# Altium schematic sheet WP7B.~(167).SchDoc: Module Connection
size C; DrawnBy: S. X. Wu; Revision: 1.0; SheetNumber: 2; SheetTotal: 2
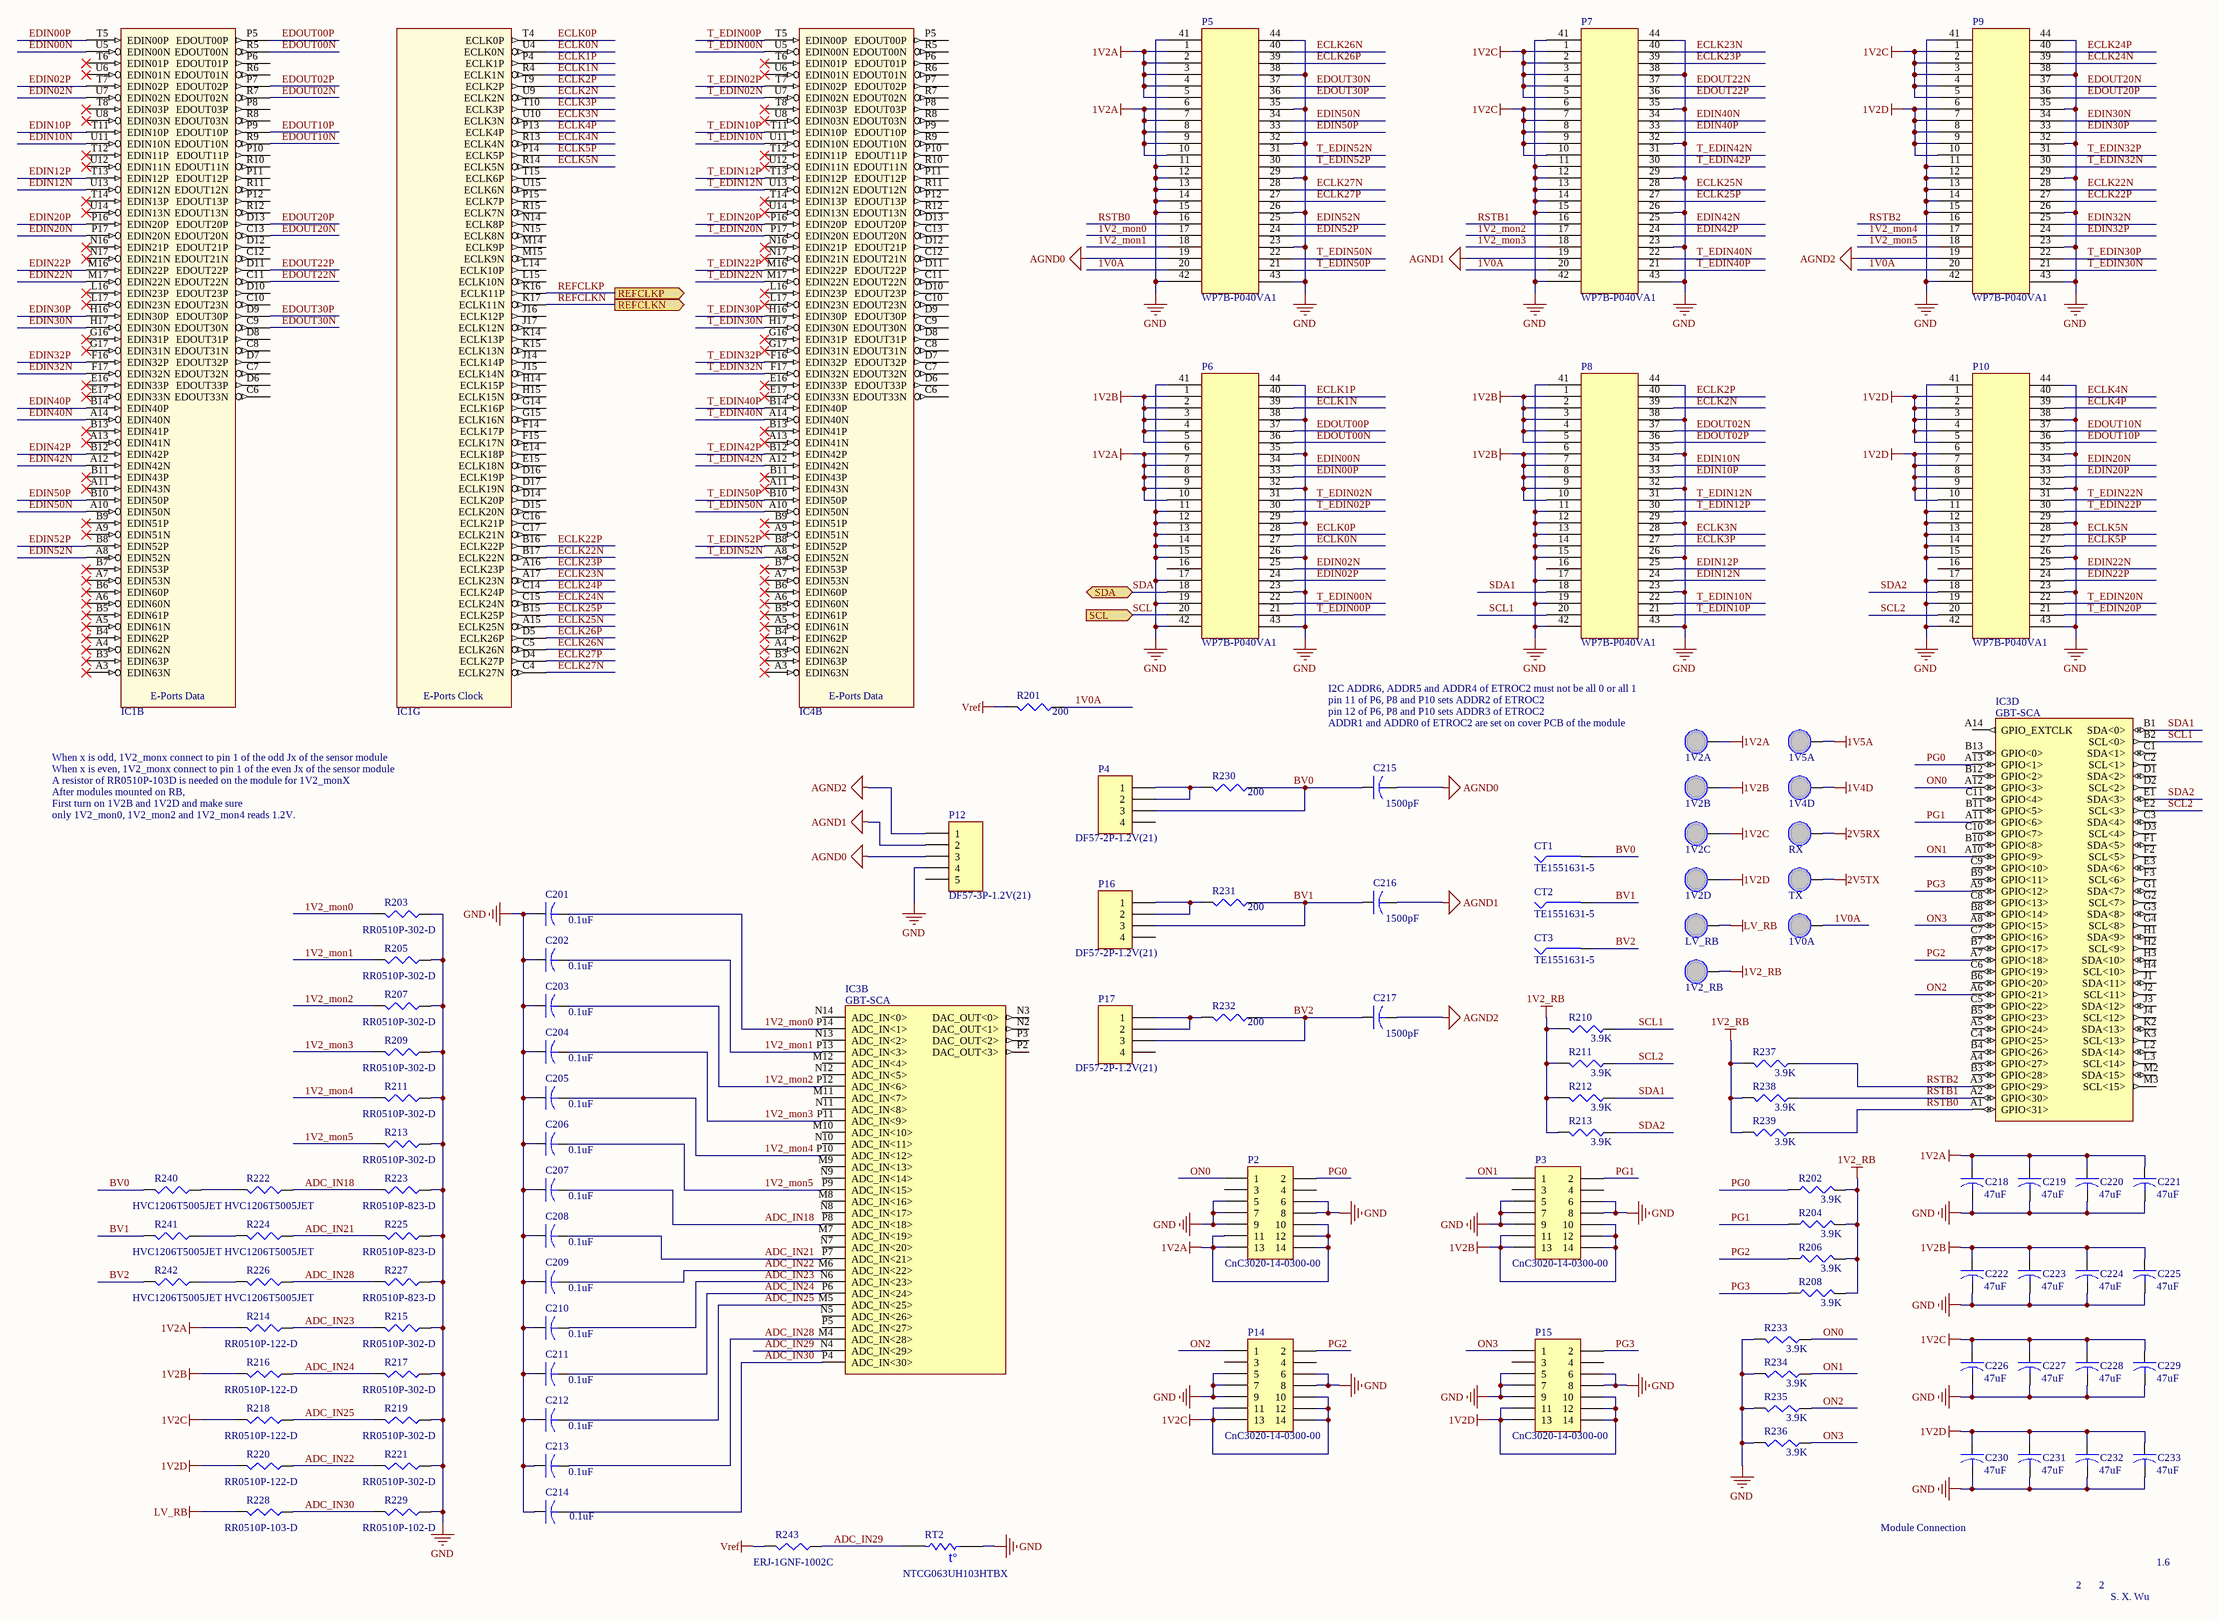
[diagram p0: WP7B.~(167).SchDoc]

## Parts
(Parts that share a designator on the sheet are numbered #1, #2 ... from top to bottom, then left to right.)
C201  value 0.1uF  [capc1005n]  (hidden comment: GRM155R71E104ME14D)
C202  value 0.1uF  [capc1005n]  (hidden comment: GRM155R71E104ME14D)
C203  value 0.1uF  [capc1005n]  (hidden comment: GRM155R71E104ME14D)
C204  value 0.1uF  [capc1005n]  (hidden comment: GRM155R71E104ME14D)
C205  value 0.1uF  [capc1005n]  (hidden comment: GRM155R71E104ME14D)
C206  value 0.1uF  [capc1005n]  (hidden comment: GRM155R71E104ME14D)
C207  value 0.1uF  [capc1005n]  (hidden comment: GRM155R71E104ME14D)
C208  value 0.1uF  [capc1005n]  (hidden comment: GRM155R71E104ME14D)
C209  value 0.1uF  [capc1005n]  (hidden comment: GRM155R71E104ME14D)
C210  value 0.1uF  [capc1005n]  (hidden comment: GRM155R71E104ME14D)
C211  value 0.1uF  [capc1005n]  (hidden comment: GRM155R71E104ME14D)
C212  value 0.1uF  [capc1005n]  (hidden comment: GRM155R71E104ME14D)
C213  value 0.1uF  [capc1005n]  (hidden comment: GRM155R71E104ME14D)
C214  value 0.1uF  [capc1005n]  (hidden comment: GRM155R71E104ME14D)
C215  value 1500pF  [venkel0805]  (hidden comment: C0805X7R102-152MNE)
C216  value 1500pF  [venkel0805]  (hidden comment: C0805X7R102-152MNE)
C217  value 1500pF  [venkel0805]  (hidden comment: C0805X7R102-152MNE)
C218  value 47uF  [capc2012n]  (hidden comment: GRM188R60J476ME15D)
C219  value 47uF  [capc2012n]  (hidden comment: GRM188R60J476ME15D)
C220  value 47uF  [capc2012n]  (hidden comment: GRM188R60J476ME15D)
C221  value 47uF  [capc2012n]  (hidden comment: GRM188R60J476ME15D)
C222  value 47uF  [capc2012n]  (hidden comment: GRM188R60J476ME15D)
C223  value 47uF  [capc2012n]  (hidden comment: GRM188R60J476ME15D)
C224  value 47uF  [capc2012n]  (hidden comment: GRM188R60J476ME15D)
C225  value 47uF  [capc2012n]  (hidden comment: GRM188R60J476ME15D)
C226  value 47uF  [capc2012n]  (hidden comment: GRM188R60J476ME15D)
C227  value 47uF  [capc2012n]  (hidden comment: GRM188R60J476ME15D)
C228  value 47uF  [capc2012n]  (hidden comment: GRM188R60J476ME15D)
C229  value 47uF  [capc2012n]  (hidden comment: GRM188R60J476ME15D)
C230  value 47uF  [capc2012n]  (hidden comment: GRM188R60J476ME15D)
C231  value 47uF  [capc2012n]  (hidden comment: GRM188R60J476ME15D)
C232  value 47uF  [capc2012n]  (hidden comment: GRM188R60J476ME15D)
C233  value 47uF  [capc2012n]  (hidden comment: GRM188R60J476ME15D)
CT1  TE1551631-5  [contact]
CT2  TE1551631-5  [contact]
CT3  TE1551631-5  [contact]
IC1  LPGBT  [BGA289X17]  (value not drawn)  (parts B,G of 8)
IC3  GBT-SCA  [bga196x14]  (parts B,D of 6)
IC4  LPGBT  [BGA289X17]  (value not drawn)  (part B of 8)
P2  CnC3020-14-0300-00  [cnc14]
P3  CnC3020-14-0300-00  [cnc14]
P4  DF57-2P-1.2V(21)  [DF57-2]
P5  WP7B-P040VA1  [wp7b-40p]
P6  WP7B-P040VA1  [wp7b-40p]
P7  WP7B-P040VA1  [wp7b-40p]
P8  WP7B-P040VA1  [wp7b-40p]
P9  WP7B-P040VA1  [wp7b-40p]
P10  WP7B-P040VA1  [wp7b-40p]
P12  DF57-3P-1.2V(21)  [DF57-3]
P14  CnC3020-14-0300-00  [cnc14]
P15  CnC3020-14-0300-00  [cnc14]
P16  DF57-2P-1.2V(21)  [DF57-2]
P17  DF57-2P-1.2V(21)  [DF57-2]
R201  Parameter 1: 200  [resc1005n]  (hidden comment: ERJ-2GEJ201X)
R202  Parameter 1: 3.9K  [resc1005n]  (hidden comment: ERJ-2GEJ392X)
R203  RR0510P-302-D  [resc1005n]
R204  Parameter 1: 3.9K  [resc1005n]  (hidden comment: ERJ-2GEJ392X)
R205  RR0510P-302-D  [resc1005n]
R206  Parameter 1: 3.9K  [resc1005n]  (hidden comment: ERJ-2GEJ392X)
R207  RR0510P-302-D  [resc1005n]
R208  Parameter 1: 3.9K  [resc1005n]  (hidden comment: ERJ-2GEJ392X)
R209  RR0510P-302-D  [resc1005n]
R210  Parameter 1: 3.9K  [resc1005n]  (hidden comment: ERJ-2GEJ392X)
R211#1  Parameter 1: 3.9K  [resc1005n]  (hidden comment: ERJ-2GEJ392X)
R211#2  RR0510P-302-D  [resc1005n]
R212  Parameter 1: 3.9K  [resc1005n]  (hidden comment: ERJ-2GEJ392X)
R213#1  Parameter 1: 3.9K  [resc1005n]  (hidden comment: ERJ-2GEJ392X)
R213#2  RR0510P-302-D  [resc1005n]
R214  RR0510P-122-D  [resc1005n]
R215  RR0510P-302-D  [resc1005n]
R216  RR0510P-122-D  [resc1005n]
R217  RR0510P-302-D  [resc1005n]
R218  RR0510P-122-D  [resc1005n]
R219  RR0510P-302-D  [resc1005n]
R220  RR0510P-122-D  [resc1005n]
R221  RR0510P-302-D  [resc1005n]
R222  HVC1206T5005JET  [resc3216n]
R223  RR0510P-823-D  [resc1005n]
R224  HVC1206T5005JET  [resc3216n]
R225  RR0510P-823-D  [resc1005n]
R226  HVC1206T5005JET  [resc3216n]
R227  RR0510P-823-D  [resc1005n]
R228  RR0510P-103-D  [resc1005n]
R229  RR0510P-102-D  [resc1005n]
R230  Parameter 1: 200  [resc1005n]  (hidden comment: ERJ-2GEJ201X)
R231  Parameter 1: 200  [resc1005n]  (hidden comment: ERJ-2GEJ201X)
R232  Parameter 1: 200  [resc1005n]  (hidden comment: ERJ-2GEJ201X)
R233  Parameter 1: 3.9K  [resc1005n]  (hidden comment: ERJ-2GEJ392X)
R234  Parameter 1: 3.9K  [resc1005n]  (hidden comment: ERJ-2GEJ392X)
R235  Parameter 1: 3.9K  [resc1005n]  (hidden comment: ERJ-2GEJ392X)
R236  Parameter 1: 3.9K  [resc1005n]  (hidden comment: ERJ-2GEJ392X)
R237  Parameter 1: 3.9K  [resc1005n]  (hidden comment: ERJ-2GEJ392X)
R238  Parameter 1: 3.9K  [resc1005n]  (hidden comment: ERJ-2GEJ392X)
R239  Parameter 1: 3.9K  [resc1005n]  (hidden comment: ERJ-2GEJ392X)
R240  HVC1206T5005JET  [resc3216n]
R241  HVC1206T5005JET  [resc3216n]
R242  HVC1206T5005JET  [resc3216n]
R243  ERJ-1GNF-1002C  [resc0603]
RT2  NTCG063UH103HTBX  [resc0603]
TP1  1V2A  [testpoint]  (no BOM)
TP2  1V2B  [testpoint]  (no BOM)
TP3  1V2C  [testpoint]  (no BOM)
TP4  1V2D  [testpoint]  (no BOM)
TP5  LV_RB  [testpoint]  (no BOM)
TP6  1V2_RB  [testpoint]  (no BOM)
TP7  1V5A  [testpoint]  (no BOM)
TP8  1V4D  [testpoint]  (no BOM)
TP9  RX  [testpoint]  (no BOM)
TP10  TX  [testpoint]  (no BOM)
TP11  1V0A  [testpoint]  (no BOM)

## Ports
REFCLKN (out), REFCLKP (out), SCL (in), SDA (bidir)

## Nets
1V2_RB: R202.2 R204.2 R206.2 R208.2 R210.2 R211#1.2 R212.2 R213#1.2 R237.2 R238.2 R239.2 TP6.1(TP)
1V2A: C218.1 C219.1 C220.1 C221.1 P2.10 P2.11 P2.12 P2.13 P2.14 P5.1 P5.2 P5.3 P5.4 P5.5 P5.6 P5.7 P5.8 P5.9 P5.10 P6.6 P6.7 P6.8 P6.9 P6.10 R214.2 TP1.1(TP)
1V2B: C222.1 C223.1 C224.1 C225.1 P3.10 P3.11 P3.12 P3.13 P3.14 P6.1 P6.2 P6.3 P6.4 P6.5 P8.1 P8.2 P8.3 P8.4 P8.5 P8.6 P8.7 P8.8 P8.9 P8.10 R216.2 TP2.1(TP)
1V2C: C226.1 C227.1 C228.1 C229.1 P7.1 P7.2 P7.3 P7.4 P7.5 P7.6 P7.7 P7.8 P7.9 P7.10 P9.1 P9.2 P9.3 P9.4 P9.5 P14.10 P14.11 P14.12 P14.13 P14.14 R218.2 TP3.1(TP)
1V2D: C230.1 C231.1 C232.1 C233.1 P9.6 P9.7 P9.8 P9.9 P9.10 P10.1 P10.2 P10.3 P10.4 P10.5 P10.6 P10.7 P10.8 P10.9 P10.10 P15.10 P15.11 P15.12 P15.13 P15.14 R220.2 TP4.1(TP)
1V4D: TP8.1(TP)
1V5A: TP7.1(TP)
2V5RX: TP9.1(TP)
2V5TX: TP10.1(TP)
AGND0: C215.2 P5.19 P12.3
AGND1: C216.2 P7.19 P12.2
AGND2: C217.2 P9.19 P12.1
GND: C201.1 C202.1 C203.1 C204.1 C205.1 C206.1 C207.1 C208.1 C209.1 C210.1 C211.1 C212.1 C213.1 C214.1 C218.2 C219.2 C220.2 C221.2 C222.2 C223.2 C224.2 C225.2 C226.2 C227.2 C228.2 C229.2 C230.2 C231.2 C232.2 C233.2 P2.5 P2.6 P2.7 P2.8 P2.9 P3.5 P3.6 P3.7 P3.8 P3.9 P5.11 P5.12 P5.13 P5.14 P5.15 P5.23 P5.26 P5.29 P5.32 P5.35 P5.38 P5.41 P5.42 P5.43 P5.44 P6.11 P6.12 P6.13 P6.14 P6.15 P6.17 P6.19 P6.23 P6.26 P6.29 P6.32 P6.35 P6.38 P6.41 P6.42 P6.43 P6.44 P7.11 P7.12 P7.13 P7.14 P7.15 P7.23 P7.26 P7.29 P7.32 P7.35 P7.38 P7.41 P7.42 P7.43 P7.44 P8.11 P8.12 P8.13 P8.14 P8.15 P8.17 P8.19 P8.23 P8.26 P8.29 P8.32 P8.35 P8.38 P8.41 P8.42 P8.43 P8.44 P9.11 P9.12 P9.13 P9.14 P9.15 P9.23 P9.26 P9.29 P9.32 P9.35 P9.38 P9.41 P9.42 P9.43 P9.44 P10.11 P10.12 P10.13 P10.14 P10.15 P10.17 P10.19 P10.23 P10.26 P10.29 P10.32 P10.35 P10.38 P10.41 P10.42 P10.43 P10.44 P12.4 P14.5 P14.6 P14.7 P14.8 P14.9 P15.5 P15.6 P15.7 P15.8 P15.9 R203.1 R205.1 R207.1 R209.1 R211#2.1 R213#2.1 R215.1 R217.1 R219.1 R221.1 R223.1 R225.1 R227.1 R229.1 R233.2 R234.2 R235.2 R236.2 RT2.1
LV_RB: R228.2 TP5.1(TP)
Vref: R201.2 R243.2
1V0A: P5.20 P7.20 P9.20 R201.1 TP11.1(TP)
1V2_mon0: C201.2 IC3.P14(ADC_IN<1>) P5.17 R203.2
1V2_mon1: C202.2 IC3.P13(ADC_IN<3>) P5.18 R205.2
1V2_mon2: C203.2 IC3.P12(ADC_IN<6>) P7.17 R207.2
1V2_mon3: C204.2 IC3.P11(ADC_IN<9>) P7.18 R209.2
1V2_mon4: C205.2 IC3.P10(ADC_IN<12>) P9.17 R211#2.2
1V2_mon5: C206.2 IC3.P9(ADC_IN<15>) P9.18 R213#2.2
ADC_IN18: C207.2 IC3.P8(ADC_IN<18>) R222.1 R223.2
ADC_IN21: C208.2 IC3.P7(ADC_IN<21>) R224.1 R225.2
ADC_IN22: C209.2 IC3.M6(ADC_IN<22>) R220.1 R221.2
ADC_IN23: C210.2 IC3.N6(ADC_IN<23>) R214.1 R215.2
ADC_IN24: C211.2 IC3.P6(ADC_IN<24>) R216.1 R217.2
ADC_IN25: C212.2 IC3.M5(ADC_IN<25>) R218.1 R219.2
ADC_IN28: C213.2 IC3.M4(ADC_IN<28>) R226.1 R227.2
ADC_IN29: IC3.N4(ADC_IN<29>) R243.1 RT2.2
ADC_IN30: C214.2 IC3.P4(ADC_IN<30>) R228.1 R229.2
BV0: C215.1 CT1.1 P4.3 R230.1 R240.2
BV1: C216.1 CT2.1 P16.3 R231.1 R241.2
BV2: C217.1 CT3.1 P17.3 R232.1 R242.2
ECLK0N: IC1.U4(ECLK0N) P6.27
ECLK0P: IC1.T4(ECLK0P) P6.28
ECLK1N: IC1.R4(ECLK1N) P6.39
ECLK1P: IC1.P4(ECLK1P) P6.40
ECLK2N: IC1.U9(ECLK2N) P8.39
ECLK2P: IC1.T9(ECLK2P) P8.40
ECLK3N: IC1.U10(ECLK3N) P8.28
ECLK3P: IC1.T10(ECLK3P) P8.27
ECLK4N: IC1.R13(ECLK4N) P10.40
ECLK4P: IC1.P13(ECLK4P) P10.39
ECLK5N: IC1.R14(ECLK5N) P10.28
ECLK5P: IC1.P14(ECLK5P) P10.27
ECLK22N: IC1.B17(ECLK22N) P9.28
ECLK22P: IC1.B16(ECLK22P) P9.27
ECLK23N: IC1.A17(ECLK23N) P7.40
ECLK23P: IC1.A16(ECLK23P) P7.39
ECLK24N: IC1.C15(ECLK24N) P9.39
ECLK24P: IC1.C14(ECLK24P) P9.40
ECLK25N: IC1.A15(ECLK25N) P7.28
ECLK25P: IC1.B15(ECLK25P) P7.27
ECLK26N: IC1.C5(ECLK26N) P5.40
ECLK26P: IC1.D5(ECLK26P) P5.39
ECLK27N: IC1.C4(ECLK27N) P5.28
ECLK27P: IC1.D4(ECLK27P) P5.27
EDIN00N: IC1.U5(EDIN00N) P6.34
EDIN00P: IC1.T5(EDIN00P) P6.33
EDIN02N: IC1.U7(EDIN02N) P6.25
EDIN02P: IC1.T7(EDIN02P) P6.24
EDIN10N: IC1.U11(EDIN10N) P8.34
EDIN10P: IC1.T11(EDIN10P) P8.33
EDIN12N: IC1.U13(EDIN12N) P8.24
EDIN12P: IC1.T13(EDIN12P) P8.25
EDIN20N: IC1.P17(EDIN20N) P10.34
EDIN20P: IC1.P16(EDIN20P) P10.33
EDIN22N: IC1.M17(EDIN22N) P10.25
EDIN22P: IC1.M16(EDIN22P) P10.24
EDIN30N: IC1.H17(EDIN30N) P9.34
EDIN30P: IC1.H16(EDIN30P) P9.33
EDIN32N: IC1.F17(EDIN32N) P9.25
EDIN32P: IC1.F16(EDIN32P) P9.24
EDIN40N: IC1.A14(EDIN40N) P7.34
EDIN40P: IC1.B14(EDIN40P) P7.33
EDIN42N: IC1.A12(EDIN42N) P7.25
EDIN42P: IC1.B12(EDIN42P) P7.24
EDIN50N: IC1.A10(EDIN50N) P5.34
EDIN50P: IC1.B10(EDIN50P) P5.33
EDIN52N: IC1.A8(EDIN52N) P5.25
EDIN52P: IC1.B8(EDIN52P) P5.24
EDOUT00N: IC1.R5(EDOUT00N) P6.36
EDOUT00P: IC1.P5(EDOUT00P) P6.37
EDOUT02N: IC1.R7(EDOUT02N) P8.37
EDOUT02P: IC1.P7(EDOUT02P) P8.36
EDOUT10N: IC1.R9(EDOUT10N) P10.37
EDOUT10P: IC1.P9(EDOUT10P) P10.36
EDOUT20N: IC1.C13(EDOUT20N) P9.37
EDOUT20P: IC1.D13(EDOUT20P) P9.36
EDOUT22N: IC1.C11(EDOUT22N) P7.37
EDOUT22P: IC1.D11(EDOUT22P) P7.36
EDOUT30N: IC1.C9(EDOUT30N) P5.37
EDOUT30P: IC1.D9(EDOUT30P) P5.36
ON0: IC3.A12(GPIO<3>) P2.1 R233.1
ON1: IC3.A10(GPIO<9>) P3.1 R234.1
ON2: IC3.A6(GPIO<21>) P14.1 R235.1
ON3: IC3.A8(GPIO<15>) P15.1 R236.1
PG0: IC3.A13(GPIO<1>) P2.2 R202.1
PG1: IC3.A11(GPIO<6>) P3.2 R204.1
PG2: IC3.A7(GPIO<18>) P14.2 R206.1
PG3: IC3.A9(GPIO<12>) P15.2 R208.1
REFCLKN: IC1.K17(ECLK11N) ; port REFCLKN
REFCLKP: IC1.K16(ECLK11P) ; port REFCLKP
RSTB0: IC3.A1(GPIO<31>) P5.16 R239.1
RSTB1: IC3.A2(GPIO<30>) P7.16 R238.1
RSTB2: IC3.A3(GPIO<29>) P9.16 R237.1
SCL: P6.20 ; port SCL
SCL1: IC3.B2(SCL<0>) P8.20 R210.1
SCL2: IC3.E2(SCL<3>) P10.20 R211#1.1
SDA: P6.18 ; port SDA
SDA1: IC3.B1(SDA<0>) P8.18 R212.1
SDA2: IC3.E1(SDA<3>) P10.18 R213#1.1
T_EDIN00N: IC4.U5(EDIN00N) P6.22
T_EDIN00P: IC4.T5(EDIN00P) P6.21
T_EDIN02N: IC4.U7(EDIN02N) P6.31
T_EDIN02P: IC4.T7(EDIN02P) P6.30
T_EDIN10N: IC4.U11(EDIN10N) P8.22
T_EDIN10P: IC4.T11(EDIN10P) P8.21
T_EDIN12N: IC4.U13(EDIN12N) P8.31
T_EDIN12P: IC4.T13(EDIN12P) P8.30
T_EDIN20N: IC4.P17(EDIN20N) P10.22
T_EDIN20P: IC4.P16(EDIN20P) P10.21
T_EDIN22N: IC4.M17(EDIN22N) P10.31
T_EDIN22P: IC4.M16(EDIN22P) P10.30
T_EDIN30N: IC4.H17(EDIN30N) P9.21
T_EDIN30P: IC4.H16(EDIN30P) P9.22
T_EDIN32N: IC4.F17(EDIN32N) P9.30
T_EDIN32P: IC4.F16(EDIN32P) P9.31
T_EDIN40N: IC4.A14(EDIN40N) P7.22
T_EDIN40P: IC4.B14(EDIN40P) P7.21
T_EDIN42N: IC4.A12(EDIN42N) P7.31
T_EDIN42P: IC4.B12(EDIN42P) P7.30
T_EDIN50N: IC4.A10(EDIN50N) P5.22
T_EDIN50P: IC4.B10(EDIN50P) P5.21
T_EDIN52N: IC4.A8(EDIN52N) P5.31
T_EDIN52P: IC4.B8(EDIN52P) P5.30
NetP4_1: P4.1 P4.2 R230.2
NetP16_1: P16.1 P16.2 R231.2
NetP17_1: P17.1 P17.2 R232.2
NetR222_2: R222.2 R240.1
NetR224_2: R224.2 R241.1
NetR226_2: R226.2 R242.1

Not connected (* = marked no-connect by the designer): IC1 A3(EDIN63N)* A4(EDIN62N)* A5(EDIN61N)* A6(EDIN60N)* A7(EDIN53N)* A9(EDIN51N)* A11(EDIN43N)* A13(EDIN41N)* B3(EDIN63P)* B4(EDIN62P)* B5(EDIN61P)* B6(EDIN60P)* B7(EDIN53P)* B9(EDIN51P)* B11(EDIN43P)* B13(EDIN41P)* C6(EDOUT33N) C7(EDOUT32N) C8(EDOUT31N) C10(EDOUT23N) C12(EDOUT21N) C16(ECLK21P) C17(ECLK21N) D6(EDOUT33P) D7(EDOUT32P) D8(EDOUT31P) D10(EDOUT23P) D12(EDOUT21P) D14(ECLK20P) D15(ECLK20N) D16(ECLK19P) D17(ECLK19N) E14(ECLK18P) E15(ECLK18N) E16(EDIN33P)* E17(EDIN33N)* F14(ECLK17P) F15(ECLK17N) G14(ECLK16P) G15(ECLK16N) G16(EDIN31P)* G17(EDIN31N)* H14(ECLK15P) H15(ECLK15N) J14(ECLK14P) J15(ECLK14N) J16(ECLK12P) J17(ECLK12N) K14(ECLK13P) K15(ECLK13N) L14(ECLK10P) L15(ECLK10N) L16(EDIN23P)* L17(EDIN23N)* M14(ECLK9P) M15(ECLK9N) N14(ECLK8P) N15(ECLK8N) N16(EDIN21P)* N17(EDIN21N)* P6(EDOUT01P) P8(EDOUT03P) P10(EDOUT11P) P11(EDOUT12P) P12(EDOUT13P) P15(ECLK7P) R6(EDOUT01N) R8(EDOUT03N) R10(EDOUT11N) R11(EDOUT12N) R12(EDOUT13N) R15(ECLK7N) T6(EDIN01P)* T8(EDIN03P)* T12(EDIN11P)* T14(EDIN13P)* T15(ECLK6P) U6(EDIN01N)* U8(EDIN03N)* U12(EDIN11N)* U14(EDIN13N)* U15(ECLK6N); IC3 A4(GPIO<27>) A5(GPIO<24>) A14(GPIO_EXTCLK) B3(GPIO<28>) B4(GPIO<26>) B5(GPIO<23>) B6(GPIO<20>) B7(GPIO<17>) B8(GPIO<14>) B9(GPIO<11>) B10(GPIO<8>) B11(GPIO<5>) B12(GPIO<2>) B13(GPIO<0>) C1(SDA<1>) C2(SCL<1>) C3(SDA<4>) C4(GPIO<25>) C5(GPIO<22>) C6(GPIO<19>) C7(GPIO<16>) C8(GPIO<13>) C9(GPIO<10>) C10(GPIO<7>) C11(GPIO<4>) D1(SDA<2>) D2(SCL<2>) D3(SCL<4>) E3(SDA<6>) F1(SDA<5>) F2(SCL<5>) F3(SCL<6>) G1(SDA<7>) G2(SCL<7>) G3(SDA<8>) G4(SCL<8>) H1(SDA<9>) H2(SCL<9>) H3(SDA<10>) H4(SCL<10>) J1(SDA<11>) J2(SCL<11>) J3(SDA<12>) J4(SCL<12>) K2(SDA<13>) K3(SCL<13>) L2(SDA<14>) L3(SCL<14>) M2(SDA<15>) M3(SCL<15>) M7(ADC_IN<19>) M8(ADC_IN<16>) M9(ADC_IN<13>) M10(ADC_IN<10>) M11(ADC_IN<7>) M12(ADC_IN<4>) N2(DAC_OUT<1>) N3(DAC_OUT<0>) N5(ADC_IN<26>) N7(ADC_IN<20>) N8(ADC_IN<17>) N9(ADC_IN<14>) N10(ADC_IN<11>) N11(ADC_IN<8>) N12(ADC_IN<5>) N13(ADC_IN<2>) N14(ADC_IN<0>) P2(DAC_OUT<3>) P3(DAC_OUT<2>) P5(ADC_IN<27>); IC4 A3(EDIN63N)* A4(EDIN62N)* A5(EDIN61N)* A6(EDIN60N)* A7(EDIN53N)* A9(EDIN51N)* A11(EDIN43N)* A13(EDIN41N)* B3(EDIN63P)* B4(EDIN62P)* B5(EDIN61P)* B6(EDIN60P)* B7(EDIN53P)* B9(EDIN51P)* B11(EDIN43P)* B13(EDIN41P)* C6(EDOUT33N) C7(EDOUT32N) C8(EDOUT31N) C9(EDOUT30N) C10(EDOUT23N) C11(EDOUT22N) C12(EDOUT21N) C13(EDOUT20N) D6(EDOUT33P) D7(EDOUT32P) D8(EDOUT31P) D9(EDOUT30P) D10(EDOUT23P) D11(EDOUT22P) D12(EDOUT21P) D13(EDOUT20P) E16(EDIN33P)* E17(EDIN33N)* G16(EDIN31P)* G17(EDIN31N)* L16(EDIN23P)* L17(EDIN23N)* N16(EDIN21P)* N17(EDIN21N)* P5(EDOUT00P) P6(EDOUT01P) P7(EDOUT02P) P8(EDOUT03P) P9(EDOUT10P) P10(EDOUT11P) P11(EDOUT12P) P12(EDOUT13P) R5(EDOUT00N) R6(EDOUT01N) R7(EDOUT02N) R8(EDOUT03N) R9(EDOUT10N) R10(EDOUT11N) R11(EDOUT12N) R12(EDOUT13N) T6(EDIN01P)* T8(EDIN03P)* T12(EDIN11P)* T14(EDIN13P)* U6(EDIN01N)* U8(EDIN03N)* U12(EDIN11N)* U14(EDIN13N)*; P2 3 4; P3 3 4; P4 4; P6 16; P8 16; P10 16; P12 5; P14 3 4; P15 3 4; P16 4; P17 4

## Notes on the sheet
- I2C ADDR6, ADDR5 and ADDR4 of ETROC2 must not be all 0 or all 1
- pin 11 of P6, P8 and P10 sets ADDR2 of ETROC2
- pin 12 of P6, P8 and P10 sets ADDR3 of ETROC2
- ADDR1 and ADDR0 of ETROC2 are set on cover PCB of the module
- A resistor of RR0510P-103D is needed on the module for 1V2_monX
- After modules mounted on RB,
- When x is odd, 1V2_monx connect to pin 1 of the odd Jx of the sensor module
- When x is even, 1V2_monx connect to pin 1 of the even Jx of the sensor module
- First turn on 1V2B and 1V2D and make sure
- only 1V2_mon0, 1V2_mon2 and 1V2_mon4 reads 1.2V.
- Module Connection
- 2
- S. X. Wu
- 1.6

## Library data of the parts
C201-C233 = C: CERAMIC CAPACITOR
CT1-CT3 = CONTACT
IC1 IC4 = LPGBT: Low Power Gigabit Transceiver; Manufacturer: CERN; Pinout Version: 180226; Bonding: No
IC3 = CERN_GBT-SCA_REV 6.2: The Slow Control Adapter ASIC for the GBT System
P2 P3 P14 P15 = Header 7X2: Header, 7-Pin, Dual row
P4 P16 P17 = Header 4: Header, 4-Pin
P5-P10 = WP7B-40P: plug
P12 = Header 5: Header, 5-Pin
R201 R202 R204 R206 R208 R210 R211#1 R212 R213#1 R230-R239 = R1: FILM RESISTOR; Text Field2: 5%
R203 R205 R207 R209 R211#2 R213#2 R214-R229 R240-R243 = R1: FILM RESISTOR; Text Field2: 1%
RT2 = Res Thermal: Thermistor
TP1-TP11 = TP: TEST POINT 40MIL DIA.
